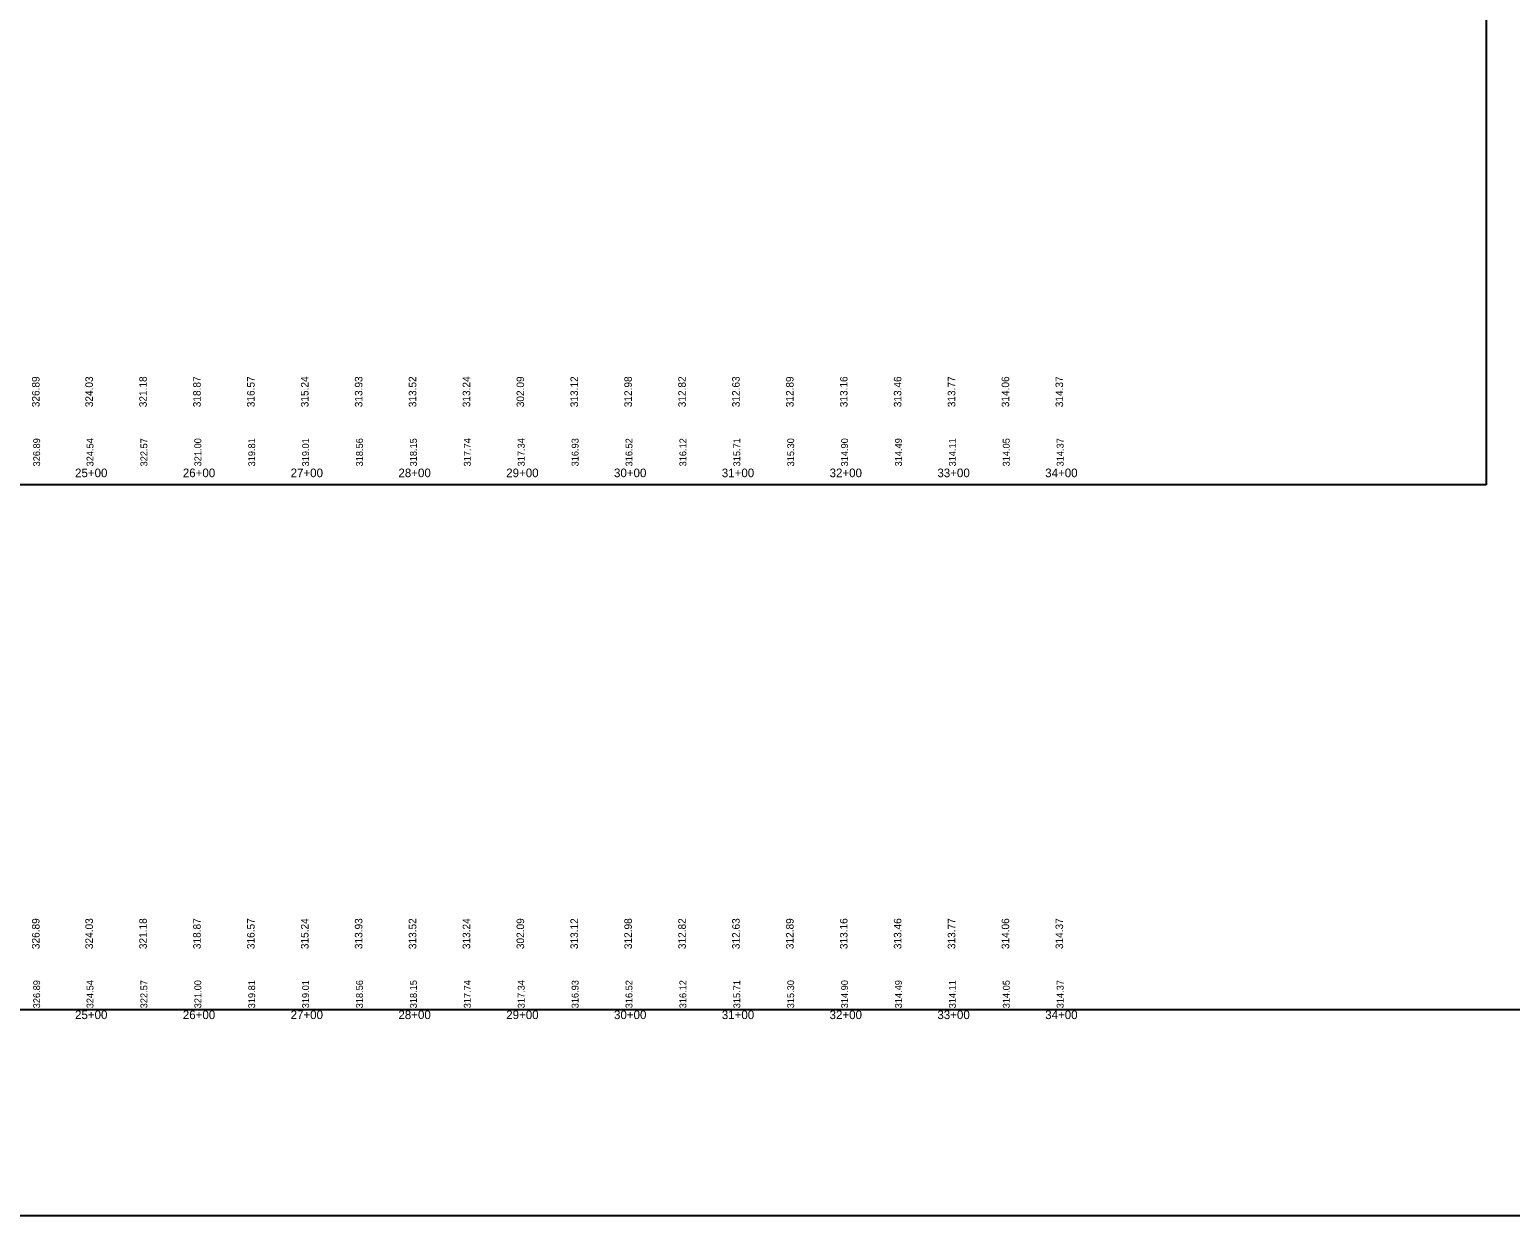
# Model space of a CAD drawing. Extents: x 2230305 to 2233905, y 1078764 to 1080964.
# Drawn here: x 2231649 to 2233023, y 1078764 to 1079864 of the extents above; entities that cross this region are included whole.
import ezdxf

# ---------------------------------------------------------------- set-up
doc = ezdxf.new("R2010")
doc.units = 0
for name, color, linetype in [('RD_DDB_StaTX', 7, 'Continuous'), ('RD_DDB_StripGrade', 7, 'Continuous'), ('RD_GPK_Profile_Cell', 7, 'Continuous'), ('RD_SHT_IplotShp', 7, 'Continuous'), ('RD_SHT_ShtClip', 7, 'Continuous')]:
    doc.layers.add(name, color=color, linetype=linetype)

msp = doc.modelspace()

# ---------------------------------------------------------------- linework, layer by layer
at = {"layer": 'RD_GPK_Profile_Cell'}
msp.add_line((2230600, 1078954.8), (2233609.3, 1078954.8), dxfattribs=at)
at = {"layer": 'RD_SHT_IplotShp'}
msp.add_lwpolyline([(2230304.7, 1078763.7), (2233904.7, 1078763.7), (2233904.7, 1080963.7), (2230304.7, 1080963.7)], close=True, dxfattribs=at)
at = {"layer": 'RD_SHT_ShtClip'}
msp.add_lwpolyline([(2233000.6, 1079441.3), (2231200.6, 1079441.3), (2231200.6, 1080541.3), (2233000.6, 1080541.3)], close=True, dxfattribs=at)

# ---------------------------------------------------------------- texts
at = {"layer": 'RD_DDB_StaTX'}
for s, p in [('25+00', (2231691.6, 1079448.5)), ('26+00', (2231791.6, 1079448.5)), ('27+00', (2231891.6, 1079448.5)), ('28+00', (2231991.6, 1079448.5)), ('29+00', (2232091.6, 1079448.5)), ('30+00', (2232191.6, 1079448.5)), ('31+00', (2232291.6, 1079448.5)), ('32+00', (2232391.6, 1079448.5)), ('33+00', (2232491.6, 1079448.5)), ('34+00', (2232591.6, 1079448.5)), ('25+00', (2231691.6, 1078945.8)), ('26+00', (2231791.6, 1078945.8)), ('27+00', (2231891.6, 1078945.8)), ('28+00', (2231991.6, 1078945.8)), ('29+00', (2232091.6, 1078945.8)), ('30+00', (2232191.6, 1078945.8)), ('31+00', (2232291.6, 1078945.8)), ('32+00', (2232391.6, 1078945.8)), ('33+00', (2232491.6, 1078945.8)), ('34+00', (2232591.6, 1078945.8))]:
    msp.add_text(s, height=8, dxfattribs=at).set_placement(p)
at = {"layer": 'RD_DDB_StripGrade'}
for s, height, p in [('326.89', 7, (2231658.7, 1079513.4)), ('324.03', 7, (2231708.2, 1079513.4)), ('321.18', 7, (2231758.2, 1079513.4)), ('318.87', 7, (2231808.2, 1079513.4)), ('316.57', 7, (2231858.2, 1079513.4)), ('315.24', 7, (2231908.2, 1079513.4)), ('313.93', 7, (2231958.2, 1079513.4)), ('313.52', 7, (2232008.2, 1079513.4)), ('313.24', 7, (2232058.2, 1079513.4)), ('302.09', 7, (2232108.2, 1079513.4)), ('313.12', 7, (2232158.2, 1079513.4)), ('312.98', 7, (2232208.2, 1079513.4)), ('312.82', 7, (2232258.2, 1079513.4)), ('312.63', 7, (2232308.2, 1079513.4)), ('312.89', 7, (2232358.2, 1079513.4)), ('313.16', 7, (2232408.2, 1079513.4)), ('313.46', 7, (2232458.2, 1079513.4)), ('313.77', 7, (2232508.2, 1079513.4)), ('314.06', 7, (2232558.2, 1079513.4)), ('314.37', 7, (2232608.2, 1079513.4)), ('326.89', 6.4, (2231659.2, 1079458.5)), ('324.54', 6.4, (2231708.7, 1079458.5)), ('322.57', 6.4, (2231758.7, 1079458.5)), ('321.00', 6.4, (2231808.7, 1079458.5)), ('319.81', 6.4, (2231858.7, 1079458.5)), ('319.01', 6.4, (2231908.7, 1079458.5)), ('318.56', 6.4, (2231958.7, 1079458.5)), ('318.15', 6.4, (2232008.7, 1079458.5)), ('317.74', 6.4, (2232058.7, 1079458.5)), ('317.34', 6.4, (2232108.7, 1079458.5)), ('316.93', 6.4, (2232158.7, 1079458.5)), ('316.52', 6.4, (2232208.7, 1079458.5)), ('316.12', 6.4, (2232258.7, 1079458.5)), ('315.71', 6.4, (2232308.7, 1079458.5)), ('315.30', 6.4, (2232358.7, 1079458.5)), ('314.90', 6.4, (2232408.7, 1079458.5)), ('314.49', 6.4, (2232458.7, 1079458.5)), ('314.11', 6.4, (2232508.7, 1079458.5)), ('314.05', 6.4, (2232558.7, 1079458.5)), ('314.37', 6.4, (2232608.7, 1079458.5)), ('326.89', 7, (2231658.7, 1079010.7)), ('324.03', 7, (2231708.2, 1079010.7)), ('321.18', 7, (2231758.2, 1079010.7)), ('318.87', 7, (2231808.2, 1079010.7)), ('316.57', 7, (2231858.2, 1079010.7)), ('315.24', 7, (2231908.2, 1079010.7)), ('313.93', 7, (2231958.2, 1079010.7)), ('313.52', 7, (2232008.2, 1079010.7)), ('313.24', 7, (2232058.2, 1079010.7)), ('302.09', 7, (2232108.2, 1079010.7)), ('313.12', 7, (2232158.2, 1079010.7)), ('312.98', 7, (2232208.2, 1079010.7)), ('312.82', 7, (2232258.2, 1079010.7)), ('312.63', 7, (2232308.2, 1079010.7)), ('312.89', 7, (2232358.2, 1079010.7)), ('313.16', 7, (2232408.2, 1079010.7)), ('313.46', 7, (2232458.2, 1079010.7)), ('313.77', 7, (2232508.2, 1079010.7)), ('314.06', 7, (2232558.2, 1079010.7)), ('314.37', 7, (2232608.2, 1079010.7)), ('326.89', 6.4, (2231659.2, 1078955.8)), ('324.54', 6.4, (2231708.7, 1078955.8)), ('322.57', 6.4, (2231758.7, 1078955.8)), ('321.00', 6.4, (2231808.7, 1078955.8)), ('319.81', 6.4, (2231858.7, 1078955.8)), ('319.01', 6.4, (2231908.7, 1078955.8)), ('318.56', 6.4, (2231958.7, 1078955.8)), ('318.15', 6.4, (2232008.7, 1078955.8)), ('317.74', 6.4, (2232058.7, 1078955.8)), ('317.34', 6.4, (2232108.7, 1078955.8)), ('316.93', 6.4, (2232158.7, 1078955.8)), ('316.52', 6.4, (2232208.7, 1078955.8)), ('316.12', 6.4, (2232258.7, 1078955.8)), ('315.71', 6.4, (2232308.7, 1078955.8)), ('315.30', 6.4, (2232358.7, 1078955.8)), ('314.90', 6.4, (2232408.7, 1078955.8)), ('314.49', 6.4, (2232458.7, 1078955.8)), ('314.11', 6.4, (2232508.7, 1078955.8)), ('314.05', 6.4, (2232558.7, 1078955.8)), ('314.37', 6.4, (2232608.7, 1078955.8))]:
    msp.add_text(s, height=height, rotation=90, dxfattribs=at).set_placement(p)

doc.saveas('drawing.dxf')
